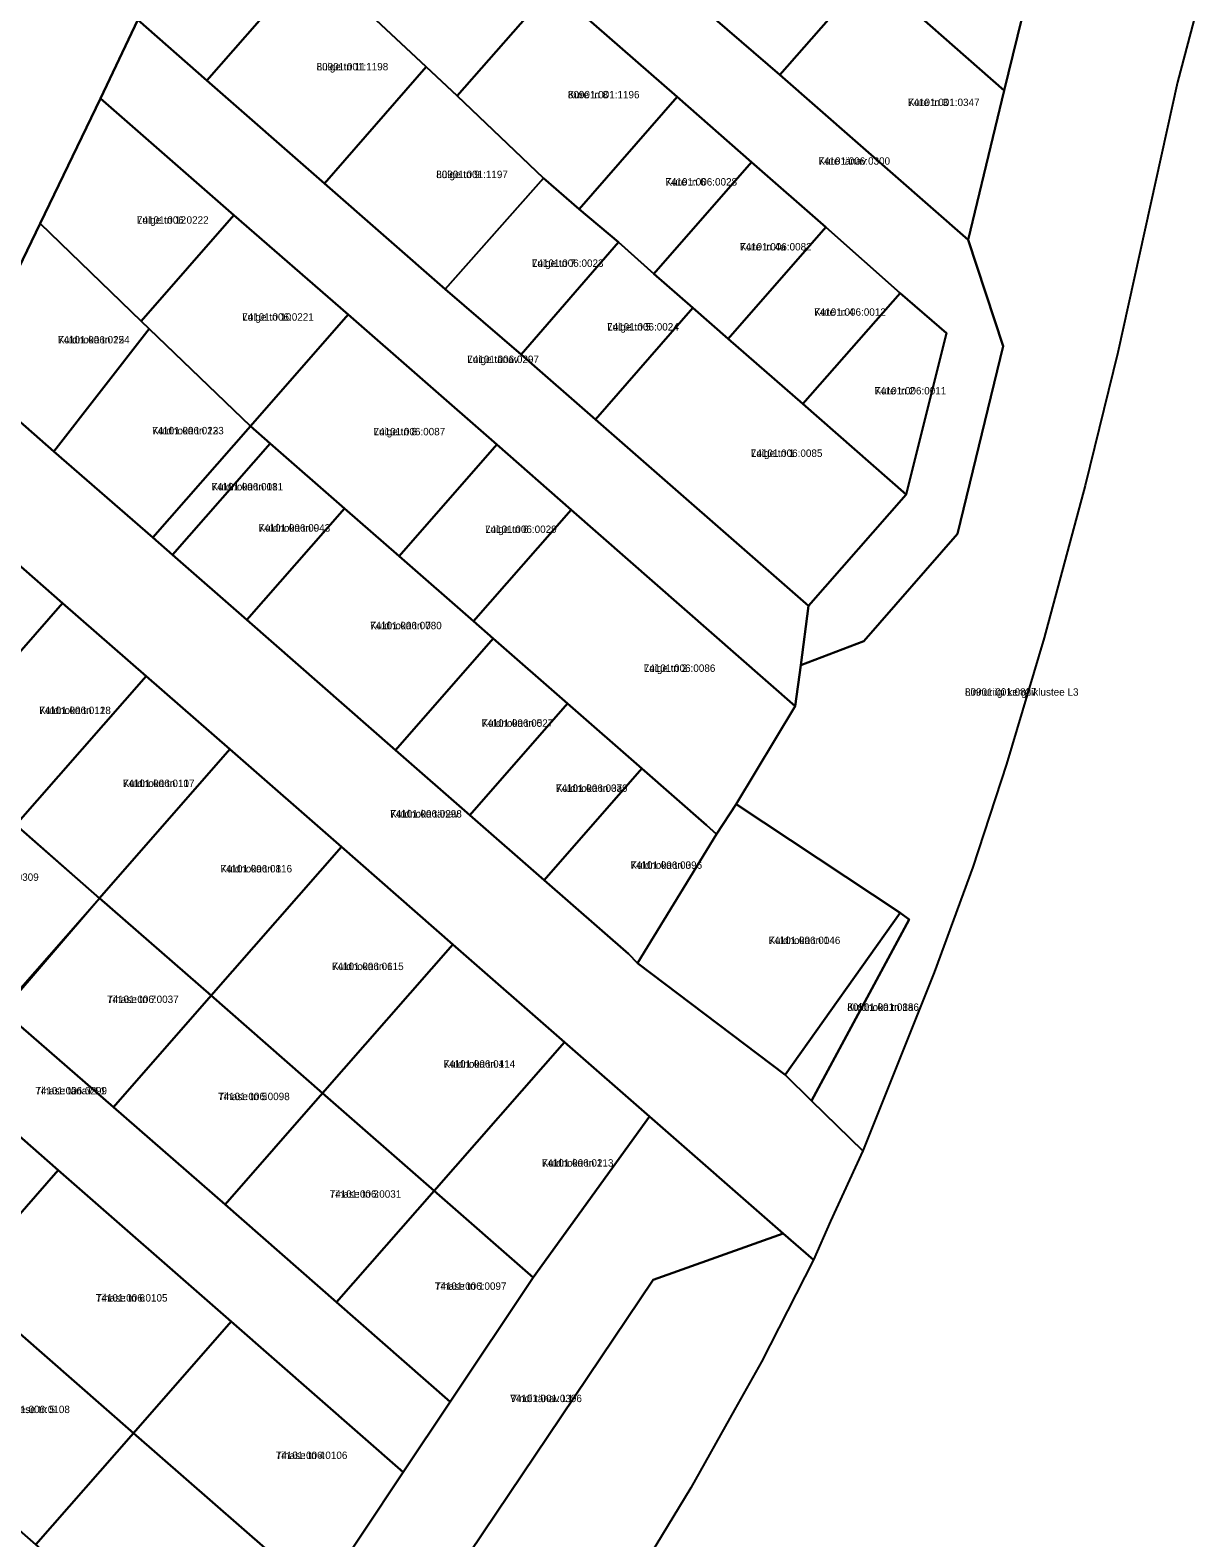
# Model space of a CAD drawing. Extents: x 524000 to 564260, y 6469338 to 6496391.
# Drawn here: x 537208.8 to 537444.2, y 6471813 to 6472118.2 of the extents above; entities that cross this region are included whole.
import ezdxf

# ---------------------------------------------------------------- set-up
doc = ezdxf.new("R2010")
doc.units = 0
for name, color, linetype in [('L_AADRESS', 7, 'Continuous'), ('PIIR', 7, 'Continuous'), ('TUNNUS', 7, 'Continuous')]:
    doc.layers.add(name, color=color, linetype=linetype)

msp = doc.modelspace()

# ---------------------------------------------------------------- linework, layer by layer
at = {"layer": 'PIIR'}
for points in [[(537265.42, 6472192.25), (537296.1, 6472165.38), (537317.27, 6472146.9), (537347.38, 6472120.42), (537360.46, 6472109.13), (537398.56, 6472075.74), (537405.65, 6472054.19), (537396.42, 6472016.25), (537377.45, 6471994.46), (537364.72, 6471989.65), (537366.28, 6472001.63), (537386.04, 6472024.21), (537394.2, 6472056.85), (537384.8, 6472064.93), (537369.81, 6472078.29), (537354.76, 6472091.47), (537339.71, 6472104.66), (537314.4, 6472126.84), (537288.07, 6472149.9), (537257.73, 6472176.48)], [(537362.76, 6472146.83), (537377.93, 6472164.11), (537386.11, 6472149.23), (537410.31, 6472124.15), (537405.9, 6472105.97), (537378.7, 6472129.92), (537360.46, 6472109.13), (537347.38, 6472120.42), (537367.31, 6472143.04)], [(537386.11, 6472149.23), (537392.74, 6472157.52), (537417.99, 6472130.95), (537444.25, 6472120.12), (537440.95, 6472107.68), (537428.89, 6472052.92), (537422.26, 6472025.98), (537413.99, 6471995.19), (537406.32, 6471969.62), (537399.54, 6471948.77), (537391.71, 6471927.38), (537377.27, 6471891.29), (537366.87, 6471901.44), (537386.65, 6471938.14), (537384.79, 6471939.52), (537351.63, 6471961.5), (537363.59, 6471981.35), (537364.72, 6471989.65), (537377.45, 6471994.46), (537396.42, 6472016.25), (537405.65, 6472054.19), (537398.56, 6472075.74), (537405.9, 6472105.97), (537410.31, 6472124.15)], [(537265.85, 6472132.37), (537244.54, 6472108), (537230.56, 6472120.27), (537245.59, 6472151.37)], [(537269.62, 6472128.83), (537288.07, 6472149.9), (537314.4, 6472126.84), (537295.17, 6472104.87), (537288.91, 6472110.75)], [(537288.91, 6472110.75), (537268.29, 6472087.18), (537244.54, 6472108), (537265.85, 6472132.37), (537269.62, 6472128.83)], [(537405.9, 6472105.97), (537398.56, 6472075.74), (537360.46, 6472109.13), (537378.7, 6472129.92)], [(537295.17, 6472104.87), (537314.4, 6472126.84), (537339.71, 6472104.66), (537319.86, 6472081.94), (537312.67, 6472088.21)], [(537230.56, 6472120.27), (537244.54, 6472108), (537268.29, 6472087.18), (537292.76, 6472065.73), (537308.15, 6472052.56), (537323.14, 6472039.4), (537366.28, 6472001.63), (537364.72, 6471989.65), (537363.59, 6471981.35), (537318.22, 6472021.1), (537303.18, 6472034.28), (537273.08, 6472060.62), (537249.99, 6472080.72), (537223.01, 6472104.37)], [(537312.67, 6472088.21), (537292.76, 6472065.73), (537268.29, 6472087.18), (537288.91, 6472110.75), (537295.17, 6472104.87)], [(537223.01, 6472104.37), (537249.99, 6472080.72), (537231.22, 6472059.28), (537210.75, 6472079.08)], [(537327.81, 6472075.29), (537319.86, 6472081.94), (537339.71, 6472104.66), (537354.76, 6472091.47), (537334.99, 6472068.89)], [(537369.81, 6472078.29), (537350.04, 6472055.72), (537342.89, 6472061.97), (537334.99, 6472068.89), (537354.76, 6472091.47)], [(537292.76, 6472065.73), (537312.67, 6472088.21), (537319.86, 6472081.94), (537327.81, 6472075.29), (537308.15, 6472052.56)], [(537210.75, 6472079.08), (537231.22, 6472059.28), (537232.82, 6472057.74), (537213.54, 6472032.88), (537195.93, 6472048.34)], [(537273.08, 6472060.62), (537253.32, 6472038.05), (537232.82, 6472057.74), (537231.22, 6472059.28), (537249.99, 6472080.72)], [(537350.04, 6472055.72), (537369.81, 6472078.29), (537384.8, 6472064.93), (537365.09, 6472042.54)], [(537308.15, 6472052.56), (537327.81, 6472075.29), (537334.99, 6472068.89), (537342.89, 6472061.97), (537323.14, 6472039.4)], [(537384.8, 6472064.93), (537394.2, 6472056.85), (537386.04, 6472024.21), (537365.09, 6472042.54)], [(537257.33, 6472034.54), (537253.32, 6472038.05), (537273.08, 6472060.62), (537303.18, 6472034.28), (537283.41, 6472011.71), (537272.38, 6472021.37)], [(537323.14, 6472039.4), (537342.89, 6472061.97), (537350.04, 6472055.72), (537365.09, 6472042.54), (537386.04, 6472024.21), (537366.28, 6472001.63)], [(537253.32, 6472038.05), (537233.56, 6472015.48), (537213.54, 6472032.88), (537232.82, 6472057.74)], [(537233.56, 6472015.48), (537253.32, 6472038.05), (537257.33, 6472034.54), (537237.57, 6472011.96)], [(537237.57, 6472011.96), (537257.33, 6472034.54), (537272.38, 6472021.37), (537252.62, 6471998.79)], [(537283.41, 6472011.71), (537303.18, 6472034.28), (537318.22, 6472021.1), (537298.45, 6471998.53)], [(537176.52, 6472026.23), (537181.76, 6472021.64), (537186.69, 6472027.32), (537215.33, 6472002.21), (537193.57, 6471977.37), (537159.73, 6472007.01)], [(537252.62, 6471998.79), (537272.38, 6472021.37), (537283.41, 6472011.71), (537298.45, 6471998.53), (537302.46, 6471995.02), (537282.71, 6471972.44)], [(537302.46, 6471995.02), (537298.45, 6471998.53), (537318.22, 6472021.1), (537363.59, 6471981.35), (537351.63, 6471961.5), (537347.68, 6471955.45), (537345.6, 6471957.27), (537332.56, 6471968.68), (537317.51, 6471981.84)], [(537215.33, 6472002.21), (537232.22, 6471987.42), (537205.87, 6471957.31), (537188.94, 6471972.13), (537193.57, 6471977.37)], [(537282.71, 6471972.44), (537302.46, 6471995.02), (537317.51, 6471981.84), (537297.75, 6471959.27)], [(537232.22, 6471987.42), (537249.15, 6471972.6), (537222.8, 6471942.49), (537205.87, 6471957.31)], [(537297.75, 6471959.27), (537317.51, 6471981.84), (537332.56, 6471968.68), (537312.8, 6471946.11)], [(537135.34, 6471979.21), (537169.19, 6471949.56), (537203.24, 6471919.68), (537225.62, 6471900.17), (537248.19, 6471880.41), (537270.76, 6471860.65), (537293.77, 6471840.51), (537284.27, 6471826.25), (537249.42, 6471856.76), (537214.43, 6471887.39), (537191.86, 6471907.15), (537164.02, 6471931.51), (537162.71, 6471930.01), (537122.84, 6471964.92)], [(537169.2, 6471949.51), (537177.78, 6471959.35), (537188.9, 6471972.12), (537205.86, 6471957.3), (537222.8, 6471942.41), (537203.05, 6471919.82)], [(537249.15, 6471972.6), (537271.73, 6471952.83), (537245.38, 6471922.74), (537222.8, 6471942.49)], [(537332.56, 6471968.68), (537345.6, 6471957.27), (537347.68, 6471955.45), (537331.64, 6471929.27), (537329.85, 6471931.18), (537312.8, 6471946.11)], [(537347.68, 6471955.45), (537351.63, 6471961.5), (537384.79, 6471939.52), (537361.58, 6471906.67), (537331.64, 6471929.27)], [(537271.73, 6471952.83), (537294.29, 6471933.08), (537267.95, 6471902.98), (537245.38, 6471922.74)], [(537222.8, 6471942.49), (537245.38, 6471922.74), (537225.62, 6471900.17), (537203.24, 6471919.68)], [(537386.65, 6471938.14), (537366.87, 6471901.44), (537361.58, 6471906.67), (537384.79, 6471939.52)], [(537294.29, 6471933.08), (537316.86, 6471913.32), (537290.52, 6471883.22), (537267.95, 6471902.98)], [(537245.38, 6471922.74), (537267.95, 6471902.98), (537248.19, 6471880.41), (537225.62, 6471900.17)], [(537316.86, 6471913.32), (537334.08, 6471898.25), (537310.55, 6471865.69), (537290.52, 6471883.22)], [(537191.86, 6471907.15), (537214.43, 6471887.39), (537194.67, 6471864.81), (537172.1, 6471884.57)], [(537248.19, 6471880.41), (537267.95, 6471902.98), (537290.52, 6471883.22), (537270.76, 6471860.65)], [(537265.89, 6471762.61), (537250.71, 6471775.89), (537267.49, 6471801.07), (537284.27, 6471826.25), (537293.77, 6471840.51), (537310.55, 6471865.69), (537334.08, 6471898.25), (537361.12, 6471874.59), (537334.86, 6471865.18)], [(537214.43, 6471887.39), (537249.42, 6471856.76), (537229.66, 6471834.18), (537194.67, 6471864.81)], [(537270.76, 6471860.65), (537290.52, 6471883.22), (537310.55, 6471865.69), (537293.77, 6471840.51)], [(537334.86, 6471865.18), (537361.12, 6471874.59), (537367.27, 6471869.25), (537356.75, 6471848.61), (537351.3, 6471838.86), (537342.47, 6471823.08), (537323.91, 6471792.5), (537313.92, 6471777.74), (537306.86, 6471767.93), (537288.37, 6471743), (537265.89, 6471762.61)], [(537194.67, 6471864.81), (537229.66, 6471834.18), (537209.9, 6471811.6), (537174.92, 6471842.23)], [(537249.42, 6471856.76), (537284.27, 6471826.25), (537267.49, 6471801.07), (537229.66, 6471834.18)], [(537229.66, 6471834.18), (537267.49, 6471801.07), (537250.71, 6471775.89), (537209.9, 6471811.6)]]:
    msp.add_lwpolyline(points, close=True, dxfattribs=at)
for points in [[(537230.56, 6472120.27), (537223.01, 6472104.37), (537210.75, 6472079.08), (537195.93, 6472048.34), (537181.45, 6472031.9), (537176.52, 6472026.23), (537159.73, 6472007.01), (537143.9, 6471988.99), (537135.34, 6471979.21), (537122.84, 6471964.92), (537104.39, 6471943.84), (537084.62, 6471921.26), (537073.06, 6471908.42), (537053.67, 6471885.9), (537033.91, 6471863.34), (537022.7, 6471850.49), (537002.94, 6471827.91), (536983.19, 6471805.36)], [(537195.93, 6472048.34), (537213.54, 6472032.88), (537233.56, 6472015.48), (537237.57, 6472011.96), (537252.62, 6471998.79), (537282.71, 6471972.44), (537297.75, 6471959.27), (537312.8, 6471946.11), (537329.85, 6471931.18), (537331.64, 6471929.27), (537361.58, 6471906.67), (537366.87, 6471901.44), (537377.27, 6471891.29), (537370.69, 6471877.06), (537367.27, 6471869.25), (537361.12, 6471874.59), (537334.08, 6471898.25), (537316.86, 6471913.32), (537294.29, 6471933.08), (537271.73, 6471952.83), (537249.15, 6471972.6), (537232.22, 6471987.42), (537215.33, 6472002.21), (537186.69, 6472027.32)]]:
    msp.add_lwpolyline(points, dxfattribs=at)

# ---------------------------------------------------------------- texts
at = {"layer": 'L_AADRESS'}
for s, p in [('Luige tn 11', (537266.72, 6472110.05)), ('Kure tn 8', (537317.57, 6472104.39)), ('Kure tn 3', (537386.39, 6472102.83)), ('Kure tänav', (537368.28, 6472090.95)), ('Luige tn 9', (537290.93, 6472088.24)), ('Kure tn 6', (537337.31, 6472086.73)), ('Luige tn 12', (537230.37, 6472079.01)), ('Kure tn 4a', (537352.4, 6472073.59)), ('Luige tn 7', (537310.29, 6472070.27)), ('Luige tn 10', (537251.66, 6472059.38)), ('Kure tn 4', (537367.42, 6472060.37)), ('Luige tn 5', (537325.52, 6472057.38)), ('Kuldnoka tn 15', (537214.38, 6472054.77)), ('Luige tänav', (537297.22, 6472050.81)), ('Kure tn 2', (537379.65, 6472044.44)), ('Kuldnoka tn 13', (537233.43, 6472036.37)), ('Luige tn 8', (537278.25, 6472036.17)), ('Luige tn 1', (537354.59, 6472031.8)), ('Kuldnoka tn 11', (537245.45, 6472025.01)), ('Kuldnoka tn 9', (537254.98, 6472016.67)), ('Luige tn 6', (537300.81, 6472016.4)), ('Kuldnoka tn 7', (537277.54, 6471996.91)), ('Luige tn 2', (537332.92, 6471988.28)), ('Linnuriigi kergliiklustee L3', (537397.94, 6471983.45)), ('Kuldnoka tn 12', (537210.58, 6471979.74)), ('Kuldnoka tn 5', (537300.11, 6471977.15)), ('Kuldnoka tn 10', (537227.51, 6471964.96)), ('Kuldnoka tn 3a', (537315.16, 6471963.98)), ('Kuldnoka tänav', (537281.61, 6471958.79)), ('Kuldnoka tn 8', (537247.26, 6471947.67)), ('Kuldnoka tn 3', (537330.24, 6471948.4)), ('Kuldnoka tn 1', (537358.21, 6471933.17)), ('Kuldnoka tn 6', (537269.84, 6471927.9)), ('Tihase tn 7', (537224.31, 6471921.24)), ('Kuldnoka tn 1a', (537374.11, 6471919.65)), ('Kuldnoka tn 4', (537292.41, 6471908.15)), ('Tihase tänav L1', (537209.8, 6471902.73)), ('Tihase tn 5', (537246.78, 6471901.57)), ('Kuldnoka tn 2', (537312.3, 6471888.11)), ('Tihase tn 3', (537269.36, 6471881.82)), ('Tihase tn 6', (537222.05, 6471860.79)), ('Tihase tn 1', (537290.65, 6471863.17)), ('Vindi tänav L1', (537305.91, 6471840.43)), ('Lõokese tn 5', (537202.29, 6471838.21)), ('Tihase tn 4', (537258.45, 6471828.92))]:
    msp.add_text(s, height=1.5, dxfattribs=at).set_placement(p)
at = {"layer": 'TUNNUS'}
for s, p in [('80901:001:1198', (537266.72, 6472110.05)), ('80901:001:1196', (537317.57, 6472104.39)), ('74101:001:0347', (537386.39, 6472102.83)), ('74101:006:0300', (537368.28, 6472090.95)), ('80901:001:1197', (537290.93, 6472088.24)), ('74101:006:0028', (537337.31, 6472086.73)), ('74101:006:0222', (537230.37, 6472079.01)), ('74101:006:0082', (537352.4, 6472073.59)), ('74101:006:0023', (537310.29, 6472070.27)), ('74101:006:0221', (537251.66, 6472059.38)), ('74101:006:0012', (537367.42, 6472060.37)), ('74101:006:0024', (537325.52, 6472057.38)), ('74101:006:0224', (537214.38, 6472054.77)), ('74101:006:0297', (537297.22, 6472050.81)), ('74101:006:0011', (537379.65, 6472044.44)), ('74101:006:0223', (537233.43, 6472036.37)), ('74101:006:0087', (537278.25, 6472036.17)), ('74101:006:0085', (537354.59, 6472031.8)), ('74101:006:0081', (537245.45, 6472025.01)), ('74101:006:0043', (537254.98, 6472016.67)), ('74101:006:0029', (537300.81, 6472016.4)), ('74101:006:0080', (537277.54, 6471996.91)), ('74101:006:0086', (537332.92, 6471988.28)), ('80901:001:0887', (537397.94, 6471983.45)), ('74101:006:0118', (537210.58, 6471979.74)), ('74101:006:0027', (537300.11, 6471977.15)), ('74101:006:0117', (537227.51, 6471964.96)), ('74101:006:0079', (537315.16, 6471963.98)), ('74101:006:0298', (537281.61, 6471958.79)), ('74101:006:0116', (537247.26, 6471947.67)), ('74101:006:0096', (537330.24, 6471948.4)), ('74101:006:0309', (537195.99, 6471945.97)), ('74101:006:0046', (537358.21, 6471933.17)), ('74101:006:0115', (537269.84, 6471927.9)), ('74101:006:0037', (537224.31, 6471921.24)), ('80901:001:0886', (537374.11, 6471919.65)), ('74101:006:0114', (537292.41, 6471908.15)), ('74101:006:0299', (537209.8, 6471902.73)), ('74101:006:0098', (537246.78, 6471901.57)), ('74101:006:0113', (537312.3, 6471888.11)), ('74101:006:0031', (537269.36, 6471881.82)), ('74101:006:0105', (537222.05, 6471860.79)), ('74101:006:0097', (537290.65, 6471863.17)), ('74101:001:0396', (537305.91, 6471840.43)), ('74101:006:0108', (537202.29, 6471838.21)), ('74101:006:0106', (537258.45, 6471828.92))]:
    msp.add_text(s, height=1.5, dxfattribs=at).set_placement(p)

doc.saveas('drawing.dxf')
